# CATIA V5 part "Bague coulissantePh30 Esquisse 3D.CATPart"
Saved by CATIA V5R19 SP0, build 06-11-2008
Part number: Bague coulissante
Bounding box of the stored display mesh (mm): x -23.769 to 23.769, y -23.596 to 23.596, z 0 to 25
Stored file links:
  C:\Users\Laurent\Desktop\Sujet National E33\CFAO Catia\Bague coulissantePh30 Esquisse 3D.CATPart
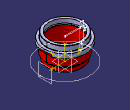
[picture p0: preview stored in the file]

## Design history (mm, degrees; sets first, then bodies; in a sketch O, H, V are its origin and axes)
Sketch1 on start face of Pad1, origin (0, 0, 0), H (1, 0, 0), V (0, -1, 0)
  circle A1 centre (0, 0) radius 23.7695
Pocket1: profile Sketch1, direction (0, 0, 1), length 1.42
Sketch2 on zx-plane, origin (0, 0, 0), H (-1, 0, 0), V (0, 0, 1)
  line L1 (15.5, 8.22) -> (15.5, 6.22)
  line L2 (15.5, 6.22) -> (31.9529, 6.22)
  line L3 (15.5, 8.22) -> (31.9529, 8.22)
  line L4 (31.9529, 8.22) -> (31.9529, 6.22)
  reference projected line E1 (14.5, 1.42) -> (-14.5, 1.42) from edge [face of Chamfer2 | end face of Pocket1]
  reference projected line E2 through (0, 0) direction (0, -1) from axis of face of Pocket2 from Sketch3.A1
  distance L3 E1 = 6.8
  distance L1 E2 = 15.5
  distance L3 L2 = 2
  vertical: L1 V, L4 V
  horizontal: L2 H, L3 H
Groove1: profile Sketch2, axis axis of face of Chamfer2, angle 360
Sketch3 on end face of Pocket1, origin (0, 0, 1.42), H (1, 0, 0), V (0, -1, 0)
  circle A1 centre (0, 0) radius 16.5
  radius A1 = 16.5
Pocket2: profile Sketch3, direction (0, 0, 1), length 6.8, outer side
Sketch4 on end face of Pocket1, origin (0, 0, 1.42), H (1, 0, 0), V (0, -1, 0)
  circle A1 centre (0, 0) radius 17.9915
  radius A1 = 17.9915
Pocket3: profile Sketch4, direction (0, 0, 1), length 14.8, outer side
Sketch5, origin (-19, 0, 0), H (0, 1, 0), V (0, 0, 1)
  line L1
  line L2
  line L3
  line L4
Pocket4: profile Sketch5, direction (-1, 0, 0), through (limit type 3)
Sketch6 on end face of Pad1, origin (0, 0, 25), H (1, 0, 0), V (0, 1, 0)
  circle A1 centre (0, 0) radius 17.45
  radius A1 = 17.45
Pocket5: profile Sketch6, direction (0, 0, -1), length 4.78, outer side
Sketch7 on xy-plane, origin (0, 0, 0), H (1, 0, 0), V (0, 1, 0)
  circle A1 centre (0, 0) radius 22.5
  radius A1 = 22.5
Pad1: profile Sketch7, direction (0, 0, 1), length 25
Sketch8 on end face of Pocket1, origin (0, 0, 1.42), H (1, 0, 0), V (0, -1, 0)
  circle A1 centre (0, 0) radius 14.2912
  radius A1 = 14.2912
Pocket6: profile Sketch8, direction (0, 0, -1), through (limit type 3)
Sketch9 on end face of Pad1, origin (0, 0, 25), H (1, 0, 0), V (0, 1, 0)
  circle A1 centre (0, 0) radius 14.95
  radius A1 = 14.95
Pocket7: profile Sketch9, direction (0, 0, -1), length 4.78
Chamfer1: length 0.9, angle 30, on edge [end face of Pocket1 | face of Pocket6 from Sketch8.A1]
Chamfer2: length 1.5, angle 45, on edge [face of Pocket2 from Sketch3.A1 | end face of Pocket1]
Sketch10 on zx-plane, origin (0, 0, 0), H (-1, 0, 0), V (0, 0, 1)
  axis line L1 (-25.6583, 20.6) -> (32.7674, 20.6)
  arc A1 centre (14.79, 20.6) radius 0.5 from (14.79, 20.1) to (14.79, 21.1) ccw
  point P3 (14.79, 20.6)
  reference projected line E1 (-17.45, 25) -> (17.45, 25) from edge [face of Pocket5 from Sketch6.A1 | end face of Pad1]
  line L2 (14.79, 20.1) -> (0, 20.1)
  point P4 (0, 20.1)
  line L3 (14.79, 21.1) -> (0, 21.1)
  point P5 (0, 21.1)
  line L4 (0, 20.1) -> (0, 21.1)
  reference projected line E2 through (0, 0) direction (0, 1) from axis of face of Pocket5 from Sketch6.A1
  distance L1 E1 = 4.4
  radius A1 = 0.5
  distance A1 E2 = 15.29
  horizontal: L1 H, L2 H, L3 H
  coincidence: P3 L1, P4 V, P5 V
  tangency: L3 A1, L2 A1
  vertical: L4 V
Groove2: profile Sketch10, axis axis of face of Pocket8 from Sketch11.A1, angle 360
Body1 (main body)
  Sketch11 on end face of Pad1, origin (0, 0, 25), H (1, 0, 0), V (0, 1, 0)
    circle A1 centre (0, 0) radius 20
    radius A1 = 20
  Pocket8: profile Sketch11, direction (0, 0, -1), length 10, outer side
  Sketch12 on end face of Pad1, origin (0, 0, 25), H (1, 0, 0), V (0, 1, 0)
    circle A1 centre (0, 0) radius 10
    radius A1 = 10
  Pocket9: profile Sketch12, direction (0, 0, -1), through (limit type 3)
  Fillet1: radius 0.3, on edge [face of Pocket5 from Sketch6.A1 | end face of Pad1]; edge [end face of Pocket5 | face of Pocket5 from Sketch6.A1]
  Fillet2: radius 0.5, on edge [face of Groove1 from Sketch2.L1 | face of Groove1]; edge [face of Groove1 from Sketch2.L2 | face of Groove1 from Sketch2.L1]
  Plane1: type Offset, Offset 19, RefPlane yz-plane
  Sketch13 on Plane1, origin (19, 0, 0), H (0, 1, 0), V (0, 0, 1)
    line L1 (-10, 18.22) -> (10, 18.22)
    line L2 (10, 18.22) -> (10, 14.8867)
    line L3 (10, 14.8867) -> (-10, 14.8867)
    line L4 (-10, 14.8867) -> (-10, 18.22)
    reference projected line E1 (20, 16.22) -> (-20, 16.22) from edge [face of Pocket8 from Sketch11.A1 | end face of Pocket3]
    reference projected line E2 through (0, 0) direction (0, -1) from axis of face of Pocket3 from Sketch4.A1
    reference projected line E3 through (0, 0) direction (0, -1) from axis of face of Pocket3 from Sketch4.A1
    distance L1 E1 = 2
    distance L2 E2 = 10
    distance L4 E3 = 10
    horizontal: L1 H, L3 H
    vertical: L2 V, L4 V
  Pocket10: profile Sketch13, direction (1, 0, 0), through (limit type 3)
  Mirror1: of Pocket10, about yz-plane
  Sketch14 on end face of Pocket1, origin (0, 0, 1.42), H (1, 0, 0), V (0, -1, 0)
    line L1 (0, 0) -> (-24.8019, 0)
    line L2 (-24.8019, 0) -> (-24.8019, -23.93)
    line L3 (-24.8019, -23.93) -> (0, -23.93)
    line L4 (0, -23.93) -> (0, 0)
    horizontal: L1 H, L3 H
    vertical: L2 V, L4 V
  Pocket11: profile Sketch14, direction (0, 0, -1), through (limit type 3), deactivated
  Sketch15 on zx-plane, origin (0, 0, 0), H (-1, 0, 0), V (0, 0, 1)
    line L1 (16.5, 2.92) -> (15, 1.42)
    point P1 (16.5, 2.92)
    point P2 (15, 1.42)
    line L2 (15, 1.42) -> (14.8109, 1.42)
    point P3 (14.8109, 1.42)
    line L3 (14.8109, 1.42) -> (14.2912, 2.32)
    point P4 (14.2912, 2.32)
    line L4 (14.2912, 2.32) -> (14.2912, 20.1)
    line L5 (14.2912, 20.1) -> (14.79, 20.1)
    arc A1 centre (14.79, 20.6) radius 0.5 from (14.79, 20.1) to (14.95, 21.0737) ccw
    line L6 (14.95, 21.0737) -> (14.95, 25)
    line L7 (14.95, 25) -> (17.15, 25)
    arc A2 centre (17.1499, 24.6999) radius 0.3001 from (17.45, 24.7) to (17.15, 25) ccw
    line L8 (17.45, 24.7) -> (17.45, 20.52)
    arc A3 centre (17.7501, 20.5201) radius 0.3001 from (17.45, 20.52) to (17.75, 20.22) ccw
    line L9 (17.75, 20.22) -> (20, 20.22)
    line L10 (20, 20.22) -> (20, 18.22)
    line L11 (20, 18.22) -> (19, 18.22)
    line L12 (19, 18.22) -> (19, 16.22)
    line L13 (19, 16.22) -> (17.9915, 16.22)
    line L14 (17.9915, 16.22) -> (17.9915, 8.22)
    line L15 (17.9915, 8.22) -> (16, 8.22)
    arc A4 centre (16.0002, 7.7198) radius 0.5002 from (16, 8.22) to (15.5, 7.72) ccw
    point P20 (15.5, 7.72)
    line L16 (15.5, 7.72) -> (15.5, 6.72)
    point P21 (15.5, 6.72)
    arc A5 centre (16.0002, 6.7202) radius 0.5002 from (15.5, 6.72) to (16, 6.22) ccw
    line L17 (16, 6.22) -> (16.5, 6.22)
    line L18 (16.5, 6.22) -> (16.5, 2.92)
    reference projected line E1 through (0, 0) direction (0, -1) from axis of face of Pocket6 from Sketch8.A1
    reference projected line E2 through (0, 0) direction (0, -1) from axis of face of Pocket6 from Sketch8.A1
    reference intersected line E3 (19, 16.22) -> (19, 18.22) from start face of Pocket4
    reference projected line E4 through (0, 0) direction (0, -1) from axis of face of Pocket6 from Sketch8.A1
    reference projected line E5 through (0, 0) direction (0, -1) from axis of face of Pocket6 from Sketch8.A1
    reference projected line E6 through (0, 0) direction (0, -1) from axis of face of Pocket6 from Sketch8.A1
    reference projected line E7 (16.5, 2.92) -> (-16.5, 2.92) from edge [face of Pocket2 from Sketch3.A1 | face of Chamfer2]
    reference projected line E8 (15, 1.42) -> (-15, 1.42) from edge [face of Chamfer2 | end face of Pocket1]
    reference projected line E9 (14.8109, 1.42) -> (-14.8109, 1.42) from edge [end face of Pocket1 | face of Chamfer1]
    reference projected line E10 (14.2912, 2.32) -> (-14.2912, 2.32) from edge [face of Chamfer1 | face of Pocket6 from Sketch8.A1]
    reference projected point E11 (0, -13.58) from edge
    reference projected point E12 (0, 27.0732) from edge
    reference intersected line E13 through (0, 8.22) direction (1, 0) from face of Groove1
    reference intersected line E14 through (0, 6.22) direction (-1, 0) from face of Groove1 from Sketch2.L2
    reference projected line E15 through (0, 0) direction (0, -1) from axis of face of Pocket6 from Sketch8.A1
    reference projected line E16 (15.5, 7.72) -> (-15.5, 7.72) from edge [face of Fillet2 | face of Groove1 from Sketch2.L1]
    reference projected line E17 (15.5, 6.72) -> (-15.5, 6.72) from edge [face of Groove1 from Sketch2.L1 | face of Fillet2]
    distance L18 E1 = 16.5 {= Sketch3.radius(A1)}
    distance L14 E2 = 17.9915 {= Sketch4.radius(A1)}
    distance L12 E3 = 0
    distance L10 E4 = 20 {= Sketch11.radius(A1)}
    distance L8 E5 = 17.45 {= Sketch6.radius(A1)}
    distance L4 E6 = 14.2912 {= Sketch8.radius(A1)}
    distance P1 E7 = 0
    distance P2 E8 = 0
    distance P3 E9 = 0
    distance P4 E10 = 0
    distance L1 E11 = 0
    distance L3 E12 = 0
    distance L15 E13 = 0
    distance L17 E14 = 0
    distance L16 E15 = 15.5
    distance P20 E16 = 0
    distance P21 E17 = 0
  Thread1: diameter 33, depth 4.8, pitch 1.5, on face of Pocket2 from Sketch3.A1, from end face of Pocket1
